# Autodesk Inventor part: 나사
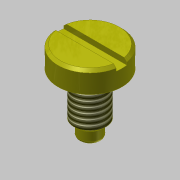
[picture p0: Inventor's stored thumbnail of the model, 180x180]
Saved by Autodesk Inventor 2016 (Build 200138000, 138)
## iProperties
Created: 2019-10
Part Number: 나사
Material: 스테인리스강
Document SubType Name: Modeling
Designer: mduedu
Density: 1 g/cm^3
Appearance: 노란색
Author: mduedu
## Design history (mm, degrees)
sketch "스케치1"
  geometry: L1 (0, 0)-(-6, 0); L2 (-6, 0)-(-6, -4); L3 (-6, -4)-(0, -4); L4 (0, -4)-(0, 0); L5 (0, -4)-(-3, -4); L6 (-3, -4)-(-3, -12.5); L7 (-3, -12.5)-(0, -12.5); L8 (0, -12.5)-(0, -4); L9 (0, -12.5)-(-2, -12.5); L10 (-2, -12.5)-(-2, -15); L11 (-2, -15)-(0, -15); L12 (0, -15)-(0, -12.5)
  constraints: 24 end point, 6 parallel, 3 horizontal, 3 perpendicular
  dimensions: "d0" = 15 distance between parallel lines of L11 L1; "d2" = 4 distance of L1.end L2.end; "d3" = 2.5 distance of L9.end L10.end; "d4" = 12 diameter of L2 L4; "d5" = 6 diameter of L6 L8; "d6" = 4 diameter of L10 L12
revolve "회전1" sketch "스케치1" stored, may be unused: angle "d7" = 90 deg
sketch "스케치2"
  geometry: L1 (2, -15)-(-2, -15) reference; L2 (-2, -15)-(-2, -12.5) reference; L3 (-2, -12.5)-(-3, -12.5) reference; L4 (-3, -12.5)-(-3, -4) reference; L5 (-3, -4)-(-6, -4) reference; L6 (-6, -4)-(-6, 0) reference; L7 (-6, 0)-(6, 0) reference; L8 (6, 0)-(6, -4) reference; L9 (6, -4)-(3, -4) reference; L10 (3, -4)-(3, -12.5) reference; L11 (3, -12.5)-(2, -12.5) reference; L12 (2, -12.5)-(2, -15) reference; L13 (0, 0)-(0, -15); L14 (-3, -4)-(-2.25, -4); L15 (-2.25, -4)-(-2.25, -4.5); L16 (-2.25, -4.5)-(-3, -4.5); L17 (-3, -4.5)-(-3, -4)
  constraints: 10 end point, 2 parallel, 1 horizontal, 1 midpoint, 1 perpendicular
  dimensions: "d8" = 4.5 diameter of L15 L13; "d10" = 0.5 distance between parallel lines of L16 L14
revolve "회전2" sketch "스케치2" stored, may be unused: angle "d11" = 90 deg
chamfer "모따기1" distance "d12" = 0.5; stored, may be unused: second distance "d13" = 2, angle "d14" = 45 deg
feature "스레드1" dims "d19" = 10, "d20" = 0
chamfer "모따기2" distance "d15" = 0.5; stored, may be unused: second distance "d16" = 2, angle "d17" = 45 deg
fillet "모깎기1" dims "d18" = 0.5
sketch "스케치3"
  geometry: L1 (-7.5, -1)-(7.5, -1); L2 (7.5, -1)-(7.5, 1); L3 (7.5, 1)-(-7.5, 1); L4 (-7.5, 1)-(-7.5, -1); L5 (-7.5, -1)-(7.5, 1); L6 (7.5, -1)-(-7.5, 1); 1 further point
  constraints: 12 end point, 2 midpoint, 2 parallel, 1 horizontal, 1 perpendicular
  dimensions: "d21" = 2 distance of L1.end L2.end; "d23" = 15 distance of L2.end L3.end
extrude "돌출1" cut sketch "스케치3" distance "d24" = 1; taper "d25" = 0 deg
node "솔리드1"
node "절단 모서리 투영1"
